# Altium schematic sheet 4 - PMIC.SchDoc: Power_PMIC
size A3; Date: 01-DEC-2018; CompanyName: Octavo Systems LLC; Address2: AUSTIN,TX; Address3: USA; DocumentNumber: DK2 RefDes; Revision: C-01; SheetNumber: 4; SheetTotal: 14
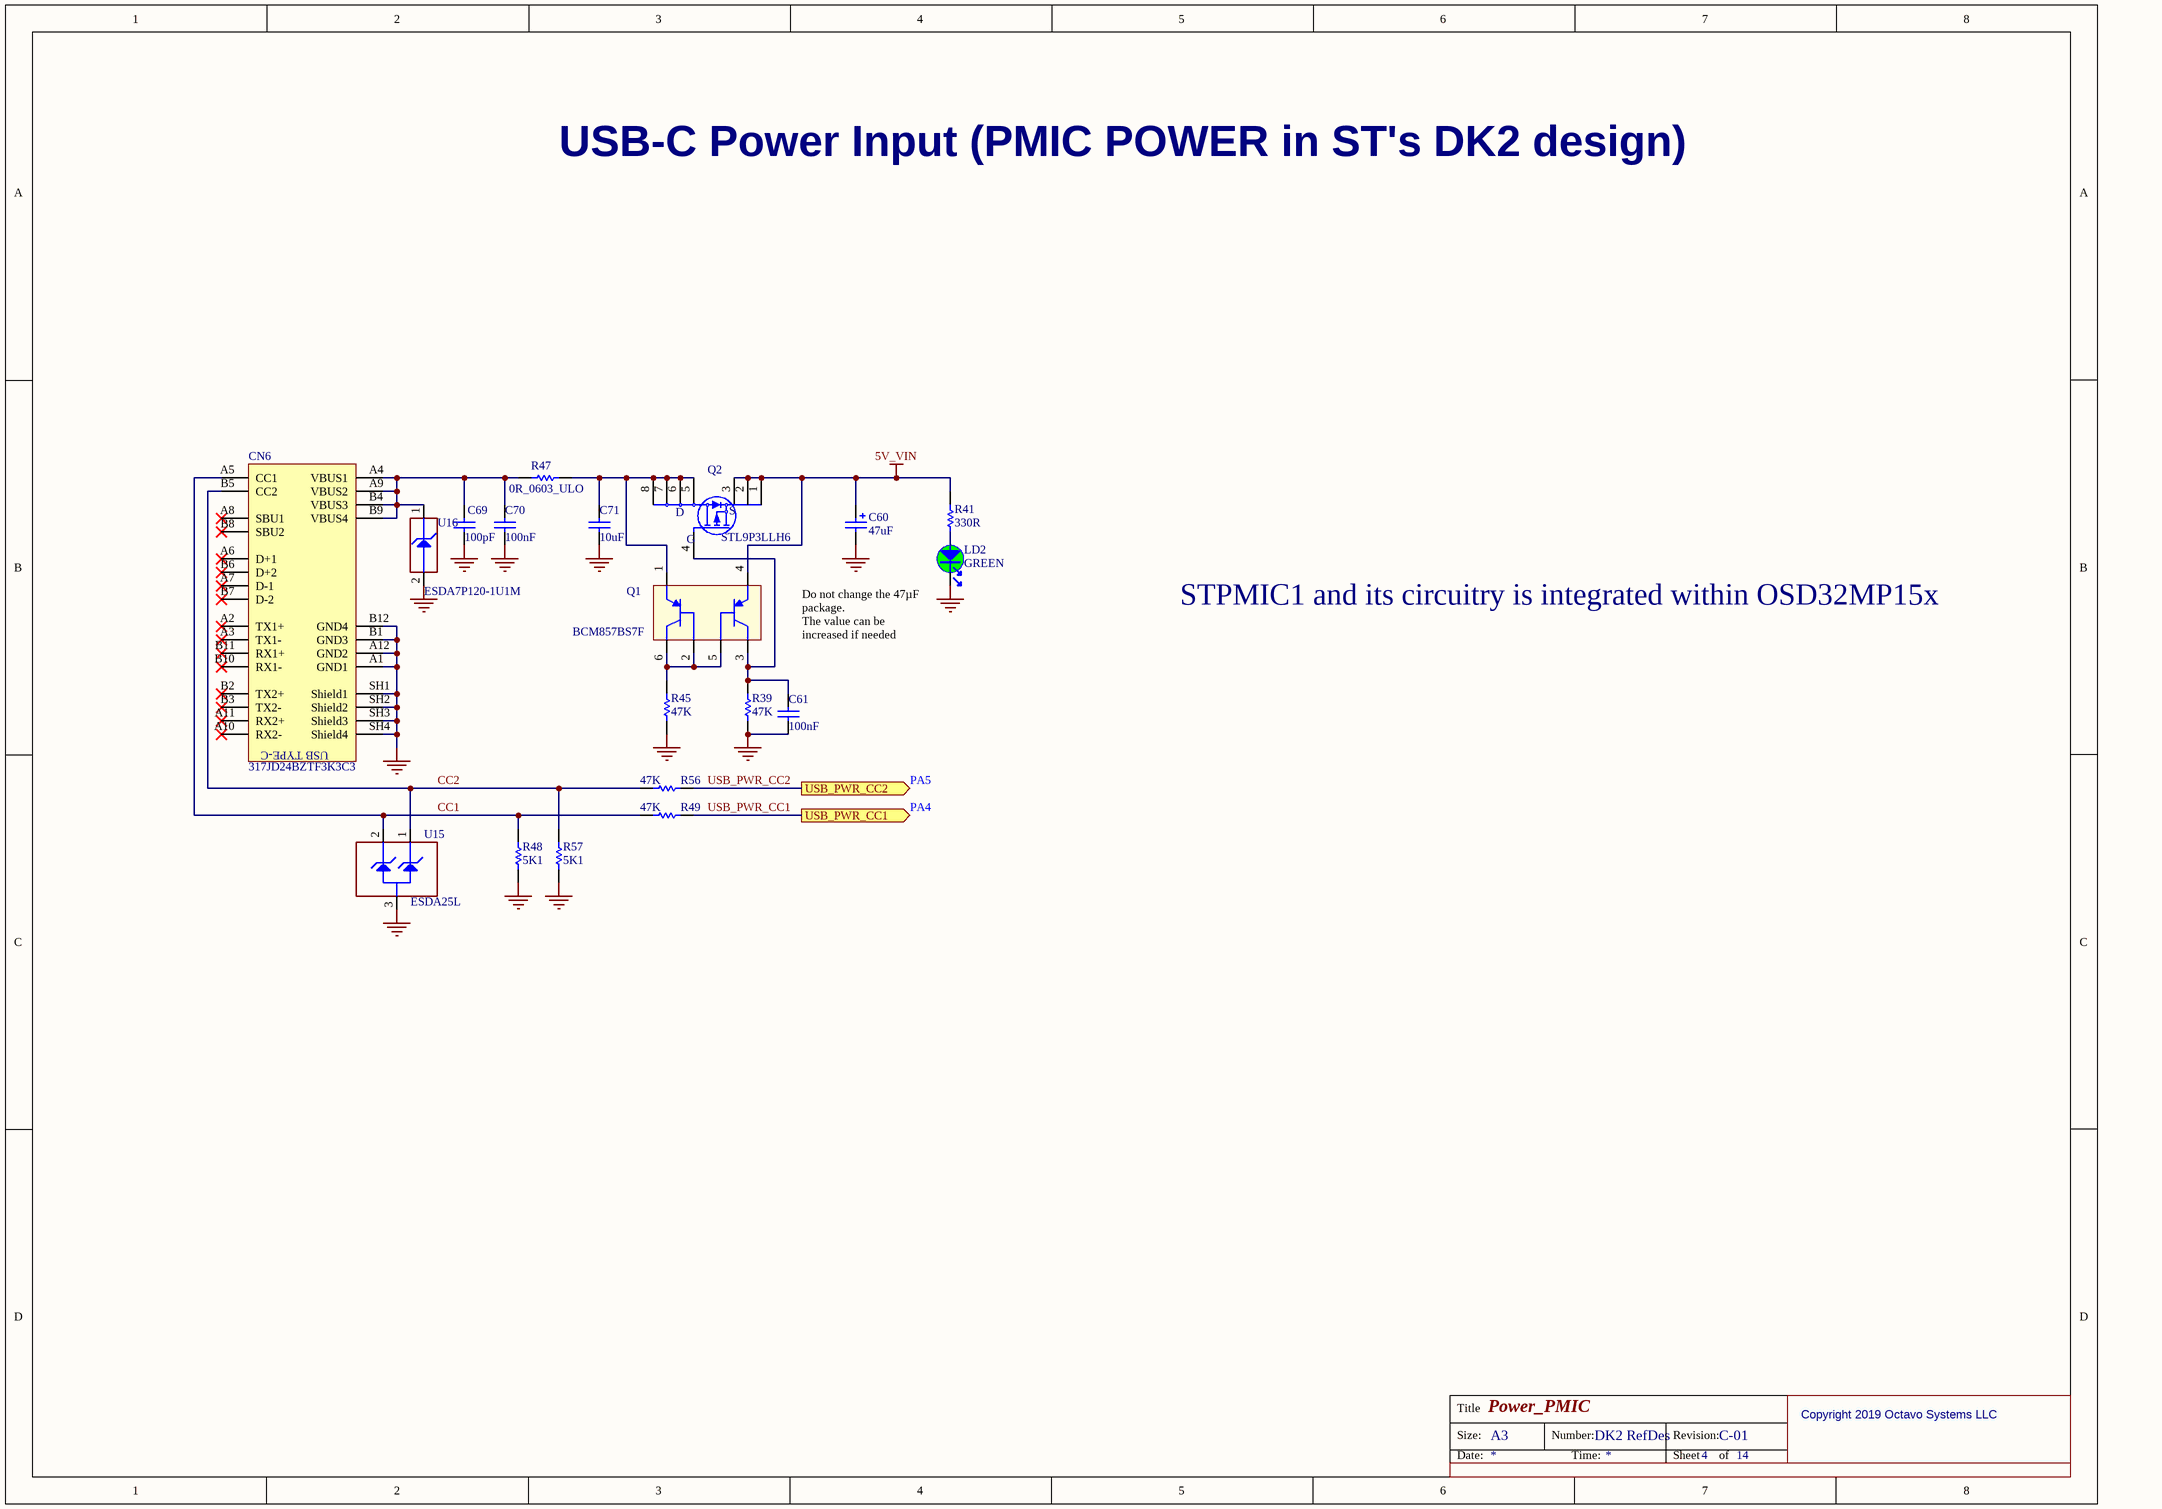
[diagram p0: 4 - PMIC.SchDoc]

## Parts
C60  value 47uF  [CPOL_TAJ-C_2312_H2P6]  (hidden comment: Cap_POL_TANA)
C61  value 100nF  [C0402]
C69  value 100pF  [C0402]  (hidden comment: Capacitor)
C70  value 100nF  [C0402]
C71  value 10uF  [C0805]  (hidden comment: Capacitor)
CN6  value 317JD24BZTF3K3C3  [CON_USB-TYPEC_COXOC_317JD24BZTF3K3C3]
LD2  value GREEN  [LED_0603_GREEN]
Q1  value BCM857BS7F  [DIO_SOT363]  (hidden comment: BCM857BS)
Q2  value STL9P3LLH6  [MOS_POWERFLAT_3P3X3P3_P065]
R39  value 47K  [R0402]  (hidden comment: Resistor)
R41  value 330R  [R0402]
R45  value 47K  [R0402]  (hidden comment: Resistor)
R47  value 0R_0603_ULO  [R0603]
R48  value 5K1  [R0402]  (hidden comment: Resistor)
R49  value 47K  [R0402]  (hidden comment: Resistor)
R56  value 47K  [R0402]  (hidden comment: Resistor)
R57  value 5K1  [R0402]  (hidden comment: Resistor)
U15  value ESDA25L  [ESD_SOT23]  (hidden comment: New schematic symbol : correction 2 diodes instead of one)
U16  value ESDA7P120-1U1M  [ESD_QFN1610_2N_1K_2A]  (hidden comment: ​Footprint needed DFN105P160X60-2N)

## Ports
USB_PWR_CC1 (out), USB_PWR_CC2 (out)

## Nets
5V_VIN: C60.1 Q1.4(E2) Q2.1(S) Q2.2(S) Q2.3(S) R41.2
GND: C60.2 C61.2 C69.1 C70.2 C71.1 CN6.A1(GND1) CN6.A12(GND2) CN6.B1(GND3) CN6.B12(GND4) CN6.SH1(Shield1) CN6.SH2(Shield2) CN6.SH3(Shield3) CN6.SH4(Shield4) LD2.2 R39.1 R45.1 R48.1 R57.1 U15.3(GND) U16.2(GND)
CC1: CN6.A5(CC1) R48.2 R49.1 U15.2(IO2)
CC2: CN6.B5(CC2) R56.1 R57.2 U15.1(IO1)
USB_PWR_CC1: R49.2 ; port USB_PWR_CC1
USB_PWR_CC2: R56.2 ; port USB_PWR_CC2
NetC61_1: C61.1 Q1.3(C2) Q2.4(G) R39.2
NetC69_2: C69.2 C70.1 CN6.A4(VBUS1) CN6.A9(VBUS2) CN6.B4(VBUS3) CN6.B9(VBUS4) R47.1 U16.1(IO1)
NetC71_2: C71.2 Q1.1(E1) Q2.5(D) Q2.6(D) Q2.7(D) Q2.8(D) R47.2
NetLD2_1: LD2.1 R41.1
NetQ1_2: Q1.2(B1) Q1.5(B2) Q1.6(C1) R45.2

Not connected (* = marked no-connect by the designer): CN6 A2(TX1+)* A3(TX1-)* A6(D+1)* A7(D-1)* A8(SBU1)* A10(RX2-)* A11(RX2+)* B2(TX2+)* B3(TX2-)* B6(D+2)* B7(D-2)* B8(SBU2)* B10(RX1-)* B11(RX1+)*

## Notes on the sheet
- USB-C Power Input (PMIC POWER in ST's DK2 design)
- (near LD2) Do not change the 47µF package.
  The value can be increased if needed
- STPMIC1 and its circuitry is integrated within OSD32MP15x
- PA5
- PA4
- Copyright 2019 Octavo Systems LLC

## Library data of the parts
C60 = MCD-00559: Capacitor, Tantalum, 47uF, 16V, 10%, TypeC; Manufacturer_Part_Number: TAJC476K016RNJ; Manufacturer: AVX; Provided_By: Subcon; Initial_Board_Reference: MB1331
C61 C70 = MCD-00006: Capacitor,100nF,16V,X7R,10%,0402; Manufacturer_Part_Number: CC0402KRX7R7BB104; Manufacturer: YAGEO; Provided_By: Subcon; Initial_Board_Reference: mb1274
C69 = MCD-00205: Capacitor, MLCC, 100pF, 50V, NPO, 5%, 0402, T=0,5mm; Manufacturer_Part_Number: CC0402JRNPO9BN101; Manufacturer: YAGEO; Provided_By: Subcon
C71 = MCD-00014: Capacitor, MLCC, 10uF, 25V, X5R, 10%, 0805, T=0,85mm; Manufacturer_Part_Number: CC0805KRX5R8BB106; Manufacturer: YAGEO; Provided_By: Subcon; Initial_Board_Reference: MB1274
CN6 = MCD-01108: USB tyce C certified receptacle for 1.6mm pcb height; Part_Type: Connector; Manufacturer: CHANT SINCERE (COXOC); ECCN_US: NA; Provided_By: Subcon; Initial_Board_Reference: MB1272
LD2 = MCD-00050: LED, Green, 0603; Part_Type: Display; Manufacturer_Part_Number: 19-213SYGC/S530-E2/TR8; Manufacturer: EVERLIGHT; ECCN_US: EAR99; ECCN_EU: NEC; Provided_By: Subcon; Initial_Board_Reference: mb1274
Q1 = MCD-01120: Transistor 45V Matched Pair PNP small Signal transistor in SOT363; Part_Type: IC; Manufacturer: DIODES_INC; ECCN_US: NA; Provided_By: Subcon; Initial_Board_Reference: MB1272
Q2 = MCD-01126: Power Mosfet, P-channel,VDS -30V,RDS 12mohm typ,ID -9A; Part_Type: IC; Manufacturer: STMICROELECTRONICS; ECCN_US: EAR99; ECCN_EU: NEC; Provided_By: Subcon; Initial_Board_Reference: MB1272
R39 R45 R49 R56 = MCD-00063: Resistor,47K,0402,1%,1/16W; Manufacturer_Part_Number: RC0402FR-0747KL; Manufacturer: YAGEO; Provided_By: Subcon; Initial_Board_Reference: MB1274
R41 = MCD-00062: Resistor,330R,0402,1%,1/16W; Manufacturer_Part_Number: RC0402FR-07330RL; Manufacturer: YAGEO; Provided_By: Subcon; Initial_Board_Reference: mb1274
R47 = MCD-00181: Resistor,0R,0603,ULO; Manufacturer_Part_Number: PMR03EZPJ000; Manufacturer: ROHM; Provided_By: Subcon
R48 R57 = MCD-00333: Resistor,5K1,0402,1%,1/16W; Manufacturer_Part_Number: RC0402FR-075K1L; Manufacturer: YAGEO; Provided_By: Subcon; Initial_Board_Reference: MB1272
U15 = MCD-01125: DUAL TRANSIL ARRAY FOR ESD PROTECTION; Part_Type: Diode; Manufacturer: STMICROELECTRONICS; ECCN_US: EAR99; ECCN_EU: NEC; Provided_By: Subcon; Initial_Board_Reference: MB1272
U16 = MCD-01026: High power transient voltage suppressor; Part_Type: Diode; Manufacturer: STMICROELECTRONICS; ECCN_US: EAR99; ECCN_EU: NEC; Provided_By: STM; Initial_Board_Reference: MB1378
